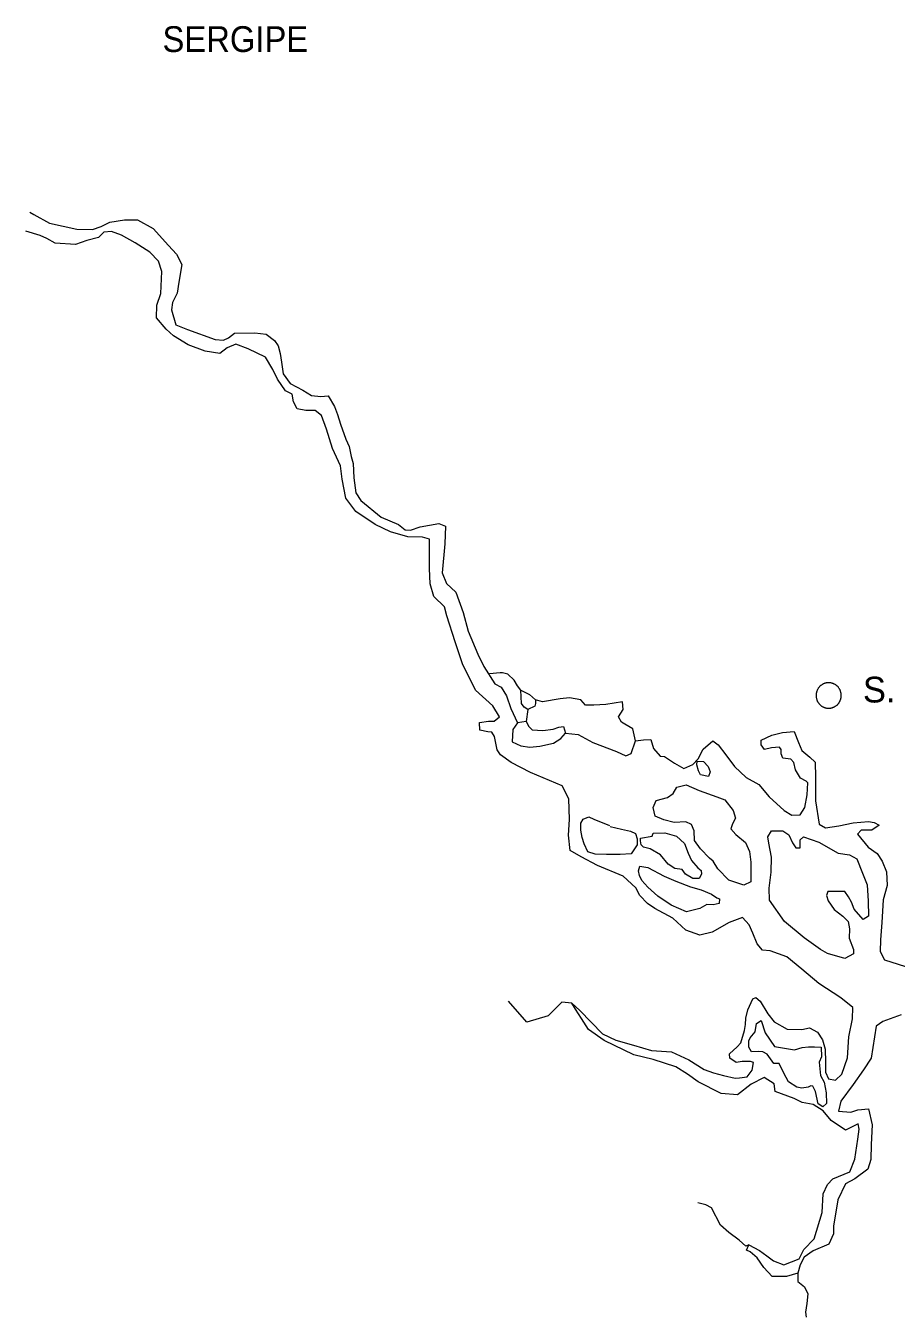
# Model space of a CAD drawing. Extents: x 47169 to 972804, y 7447977 to 9608469.
# Drawn here: x 674656 to 697299, y 8765455 to 8799042 of the extents above; entities that cross this region are included whole.
import ezdxf

# ---------------------------------------------------------------- set-up
doc = ezdxf.new("R2010")
doc.units = 0
doc.header["$LTSCALE"] = 270
doc.layers.add('1', color=7, linetype='Continuous', lineweight=13)
doc.layers.add('3', color=7, linetype='Continuous')

msp = doc.modelspace()

# ---------------------------------------------------------------- linework, layer by layer
at = {"layer": '1'}
for points in [[(674756.8, 8794197.7), (674865.8, 8794130.7), (675269.1, 8793907.4), (675978.9, 8793748.8), (676394.3, 8793746.5), (676613.3, 8793822.8), (676843.5, 8793932.2), (677226.5, 8793996.5), (677565.4, 8793994.7), (677968.7, 8793771.3), (678370.8, 8793326.7), (678577.3, 8793104.3), (678718, 8792838.1), (678639, 8792373.9), (678593.7, 8792086.5), (678472.2, 8791843.8), (678449.3, 8791655.9), (678556.5, 8791268.2), (678861.9, 8791144.9), (679582, 8790886.5), (679800.5, 8790863.2), (679932.1, 8790928.9), (680085.8, 8791049.7), (680610.6, 8791057.9), (680905.5, 8791023.1), (681123.2, 8790856), (681220.9, 8790722.7), (681274.5, 8790523.3), (681306, 8790290.8), (681348.1, 8789991.9), (681532.5, 8789736.5), (681859.5, 8789568.8), (682088.3, 8789423.7), (682328.7, 8789400.2), (682525.5, 8789421.3), (682688, 8789143.8), (682763.3, 8788933.2), (682838.4, 8788678.4), (682978.4, 8788290.4), (683064.8, 8788101.9), (683117.9, 8787836.1), (683171.6, 8787658.8), (683191.4, 8787282.6), (683243.9, 8786895.2), (683373.9, 8786695.3), (683896.2, 8786261), (684354.2, 8786070.4), (684528.3, 8785936.6), (684659.4, 8785924.8), (684911.3, 8786011.9), (685403.7, 8786097.7), (685578.2, 8786030.3), (685553.7, 8785565.8), (685483.9, 8784814), (685602.5, 8784536.8), (685841.7, 8784314.2), (686035.5, 8783782.1), (686163.8, 8783294.6), (686411.8, 8782695.9), (686573.9, 8782374.2), (686855.6, 8781930.1), (687019, 8781840.6), (687159.8, 8781618.6), (687278.1, 8781286), (687450.8, 8780908.9), (687329.7, 8780743.7), (687306, 8780423), (687534.8, 8780311.1), (687764.1, 8780276.6), (688026.6, 8780308.3), (688387.7, 8780383.6), (688574.2, 8780504.2), (688695.2, 8780647.3), (689022.9, 8780612.3), (689404.2, 8780399.9), (690025.7, 8780164), (690265.5, 8780052), (690408, 8780117.5), (690519.2, 8780448.7), (690727, 8780469.6), (690912.8, 8780479.6), (690988, 8780246.9), (691161.7, 8780046.7), (691270.9, 8780035), (691532.2, 8779867.6), (691771.8, 8779722.3), (692012.8, 8779831.6), (692144.8, 8779974.6), (692277.5, 8780228.2), (692530.1, 8780448), (692671.6, 8780336.6), (692866.8, 8780081), (693094.5, 8779780.9), (693398.8, 8779491.5), (693725.6, 8779312.6), (693996.9, 8778990.2), (694388.2, 8778633.8), (694584.2, 8778511), (694802.8, 8778520.7), (694924.2, 8778708.1), (694980.8, 8779039.6)], [(682638.2, 8788049), (682477, 8788547.7), (682347.8, 8788902.3), (682184.5, 8789036), (681944, 8789037.3), (681714.7, 8789082.8), (681617.3, 8789260.4), (681585.6, 8789459.6), (681411.2, 8789549.1), (681205.2, 8789848.9), (681086.3, 8790104), (680891.3, 8790425.8), (680444.3, 8790638.5), (680117, 8790761.9), (679897.8, 8790663.6), (679700.3, 8790520.8), (679318, 8790578.2), (678881.6, 8790746.5), (678500.3, 8790980.9), (678304.4, 8791147.9), (678054.6, 8791447.9), (678067.3, 8791779.7), (678167.3, 8792077.8), (678192.3, 8792652.9), (678106.3, 8792918.8), (677877.9, 8793152.3), (677496.6, 8793397.7), (677147.8, 8793598.7), (676885.9, 8793688.6), (676689.1, 8793678.6), (676546.2, 8793535.6), (676239.7, 8793459.8), (675944, 8793350.7), (675419.4, 8793386.7), (675201.4, 8793509.5), (675026.9, 8793587.9), (674655.8, 8793700.4)], [(690931, 8772392.9), (691455.3, 8772356.6), (691902, 8772143.8), (692304.8, 8771898), (692544.7, 8771808.1), (692806.5, 8771740.2), (693112, 8771672), (693221.3, 8771682.4), (693418.1, 8771703.3), (693550.3, 8771879.6), (693584.3, 8772078.5), (693507.9, 8772101.1), (693289.4, 8772102.4), (693136.3, 8772081.2), (692973.1, 8772192.7), (692962.8, 8772303.4), (693160.6, 8772490.3), (693259.5, 8772589.3), (693348.8, 8772909.6), (693382.5, 8773064.3), (693383.5, 8773230.2), (693439.5, 8773451.1), (693572.3, 8773737.9), (693649, 8773770.7), (693757.6, 8773670.5), (693963.3, 8773348.4), (694126, 8773137.3), (694463.6, 8772947.2), (694845.9, 8772933.8), (695042.9, 8772976.9), (695249.8, 8772865), (695379.7, 8772665.1), (695454.7, 8772421.3), (695463.7, 8772089.3), (695462.1, 8771823.9), (695537.6, 8771657.5), (695723.1, 8771623.2), (695887.9, 8771777.1), (696032.5, 8772196.6), (696068.6, 8772749.5), (696158.8, 8773213.6), (696171.5, 8773512.2), (695856.1, 8773757.5), (695290.2, 8774137), (694844.4, 8774504.7), (694453, 8774827.9), (694016.8, 8774985.4), (693820.2, 8774997.6), (693679.1, 8775164.4), (693571.5, 8775441.6), (693474.5, 8775663.4), (693300.7, 8775852.5), (692950.3, 8775721.8), (692511.7, 8775470), (692194.4, 8775394.4), (691823.6, 8775518.3), (691486.6, 8775830), (691018.3, 8776087.2), (690833.2, 8776210), (690626.8, 8776421.4), (690529.7, 8776621.1), (690192.7, 8776921.7), (689527.7, 8777202.2), (689102.8, 8777425.9), (688819.7, 8777593.4), (688778.2, 8777991.9), (688802.5, 8778401.1), (688783.7, 8778932.2), (688610.8, 8779276.1), (687782.2, 8779623.8), (687281, 8779881.1), (687009, 8780081.8), (686922.3, 8780215), (686847.7, 8780558.4), (686782.8, 8780669.4), (686673.6, 8780681.1), (686466.2, 8780726.5), (686456.4, 8780925.7), (686697, 8780957.5), (686839.1, 8780956.7), (686981.8, 8781066.5), (686808.6, 8781355.1), (686351.9, 8781767), (686016.9, 8782443.7), (685823.5, 8783020), (685608.7, 8783696), (685544.4, 8783928.7), (685272.7, 8784195.7), (685176.2, 8784528.1), (685156.6, 8784926.5), (685159.5, 8785435.3), (685160.9, 8785689.7), (684975.4, 8785746.1), (684592.8, 8785748.2), (684145.5, 8785883.5), (683742.1, 8786073.8), (683241.2, 8786408.4), (682980.8, 8786752.8), (682885.2, 8787251.1), (682843.3, 8787594.3), (682638.2, 8788049)], [(687532.2, 8781760.2), (687445.4, 8781871.4), (687358.9, 8782026.8), (687195.8, 8782182.6), (687053.9, 8782216.5), (686999.3, 8782216.9), (686714.9, 8782185.3)], [(690519.2, 8780448.7), (690444.5, 8780758.9), (690237.6, 8780881.8), (690150.4, 8780926.6), (690074.7, 8781070.8), (690196, 8781258.2), (690175.3, 8781457.4), (689748.7, 8781393.5), (689431.7, 8781373.2), (689213.1, 8781374.5), (689093.6, 8781507.9), (688798.9, 8781564.9), (688558.2, 8781533.1), (688098.8, 8781458.3), (687913.3, 8781514.7), (687912.8, 8781415.2), (687901.4, 8781348.8), (687715.1, 8781261.4), (687617.1, 8781317.3), (687552.1, 8781417.2), (687532.2, 8781760.2), (687761.1, 8781648.3), (687913.3, 8781514.7)], [(695870.5, 8781622.9), (695870.6, 8781634), (695869.6, 8781646.2), (695868.6, 8781657.3), (695867.5, 8781669.4), (695865.4, 8781680.5), (695863.3, 8781691.6), (695861.2, 8781703.8), (695858, 8781714.8), (695854.8, 8781725.9), (695851.6, 8781737), (695847.2, 8781747), (695842.9, 8781758.1), (695838.6, 8781769.2), (695833.2, 8781779.2), (695827.8, 8781789.1), (695821.3, 8781799.1), (695815.9, 8781809.1), (695809.4, 8781818), (695801.8, 8781828), (695795.3, 8781836.9), (695787.7, 8781845.8), (695780.1, 8781853.6), (695771.4, 8781862.5), (695763.8, 8781870.3), (695755.1, 8781878.1), (695746.4, 8781884.8), (695736.6, 8781892.6), (695727.9, 8781899.3), (695718.1, 8781904.8), (695708.3, 8781911.6), (695698.5, 8781917.1), (695688.7, 8781922.7), (695677.8, 8781927.2), (695666.9, 8781931.7), (695657.1, 8781936.2), (695646.2, 8781939.6), (695635.3, 8781943), (695624.4, 8781946.3), (695612.4, 8781948.6), (695601.5, 8781950.9), (695590.5, 8781953.2), (695578.5, 8781954.4), (695567.6, 8781955.5), (695555.6, 8781956.7), (695544.7, 8781956.8), (695533.7, 8781956.8), (695521.7, 8781955.8), (695510.8, 8781954.8), (695498.7, 8781953.7), (695487.8, 8781951.6), (695476.8, 8781949.4), (695464.8, 8781947.3), (695453.9, 8781944.1), (695442.9, 8781940.8), (695432, 8781937.5), (695422.1, 8781933.2), (695411.1, 8781928.8), (695400.2, 8781924.5), (695390.3, 8781919), (695380.5, 8781913.5), (695370.6, 8781906.9), (695360.7, 8781901.5), (695351.9, 8781894.9), (695342, 8781887.2), (695333.3, 8781880.6), (695324.5, 8781872.9), (695316.8, 8781865.2), (695308, 8781856.4), (695300.3, 8781848.7), (695292.6, 8781839.9), (695286, 8781831.1), (695278.2, 8781821.2), (695271.6, 8781812.4), (695266.1, 8781802.5), (695259.5, 8781792.5), (695254, 8781782.6), (695248.5, 8781772.7), (695244, 8781761.7), (695239.6, 8781750.6), (695235.2, 8781740.7), (695231.8, 8781729.7), (695228.5, 8781718.6), (695225.1, 8781707.6), (695222.8, 8781695.4), (695220.6, 8781684.4), (695218.3, 8781673.3), (695217.2, 8781661.2), (695216, 8781650.1), (695214.9, 8781637.9), (695214.8, 8781626.9), (695214.7, 8781615.8), (695215.8, 8781603.6), (695216.8, 8781592.6), (695217.8, 8781580.4), (695219.9, 8781569.3), (695222, 8781558.2), (695224.2, 8781546.1), (695227.4, 8781535), (695230.6, 8781523.9), (695233.8, 8781512.8)], [(695233.8, 8781512.8), (695238.1, 8781502.8), (695242.4, 8781491.7), (695246.7, 8781480.7), (695252.1, 8781470.7), (695257.5, 8781460.7), (695264, 8781450.7), (695269.4, 8781440.7), (695275.9, 8781431.8), (695283.5, 8781421.8), (695290, 8781412.9), (695297.6, 8781404), (695305.2, 8781396.2), (695313.9, 8781387.3), (695321.5, 8781379.5), (695330.2, 8781371.7), (695338.9, 8781365.1), (695348.7, 8781357.2), (695357.4, 8781350.6), (695367.2, 8781345), (695377, 8781338.3), (695386.8, 8781332.7), (695396.6, 8781327.1), (695407.5, 8781322.6), (695418.4, 8781318.1), (695428.2, 8781313.6), (695439.1, 8781310.2), (695450.1, 8781306.9), (695461, 8781303.5), (695473, 8781301.2), (695483.9, 8781298.9), (695494.8, 8781296.6), (695506.8, 8781295.4), (695517.7, 8781294.3), (695529.8, 8781293.1), (695540.7, 8781293.1), (695551.6, 8781293), (695563.6, 8781294), (695574.6, 8781295.1), (695586.6, 8781296.1), (695597.6, 8781298.2), (695608.5, 8781300.4), (695620.5, 8781302.5), (695631.5, 8781305.8), (695642.4, 8781309), (695653.4, 8781312.3), (695663.2, 8781316.7), (695674.2, 8781321), (695685.2, 8781325.4), (695695, 8781330.8), (695704.9, 8781336.3), (695714.8, 8781342.9), (695724.6, 8781348.4), (695733.4, 8781354.9), (695743.3, 8781362.6), (695752.1, 8781369.2), (695760.9, 8781376.9), (695768.6, 8781384.6), (695777.4, 8781393.4), (695785.1, 8781401.1), (695792.8, 8781409.9), (695799.4, 8781418.7), (695807.1, 8781428.6), (695813.7, 8781437.4), (695819.2, 8781447.4), (695825.8, 8781457.3), (695831.4, 8781467.2), (695836.9, 8781477.1), (695841.3, 8781488.2), (695845.8, 8781499.2), (695850.2, 8781509.1), (695853.5, 8781520.2), (695856.9, 8781531.2), (695860.2, 8781542.3), (695862.5, 8781554.4), (695864.7, 8781565.5), (695867, 8781576.5), (695868.2, 8781588.7), (695869.3, 8781599.7), (695870.5, 8781611.9), (695870.5, 8781622.9)], [(687715.1, 8781261.4), (687669.7, 8780951.9), (687450.8, 8780908.9)], [(687669.7, 8780951.9), (687745.4, 8780818.8), (687832.3, 8780729.8), (688105.5, 8780717.1), (688378.9, 8780748.7), (688521.2, 8780803.2), (688641.5, 8780813.6), (688695.2, 8780647.3)], [(694980.8, 8779039.6), (695004.5, 8779349.2), (694961, 8779393.7), (694808.5, 8779472.1), (694678.7, 8779694.1), (694636.1, 8779882.4), (694560.1, 8779971.4), (694352.6, 8779994.7), (694309.5, 8780105.6), (694310.2, 8780216.2), (694266.9, 8780282.9), (694059.1, 8780262), (693873.1, 8780218.8), (693786.3, 8780341), (693787.1, 8780462.7), (694061.1, 8780593.8), (694345.6, 8780658.5), (694640.9, 8780690), (694759.4, 8780401.6), (694845.6, 8780190.9), (695052.2, 8780023.8), (695193.5, 8779890.2), (695202.1, 8779502.9), (695198.4, 8778883.4), (695293.1, 8778274.4), (695456.5, 8778184.9), (695806.6, 8778238.2), (696178.6, 8778313.4), (696583.1, 8778344.1), (696725.1, 8778321.1), (696855.8, 8778254), (696669.2, 8778122.3), (696385.1, 8778124.1), (696297, 8778014), (696568.2, 8777680.4), (696807.6, 8777513.1), (696937.5, 8777313.2), (697045.2, 8777035.9), (697064.9, 8776681.8), (696964.2, 8776306.3), (696927.9, 8775720.2), (696892.4, 8775266.8), (696879.7, 8774968.2), (696998.5, 8774746.2), (697707.4, 8774520.7)], [(689861.4, 8778217.9), (690156.1, 8778149.9), (690385.2, 8778093.2), (690516.1, 8778037.1), (690558.9, 8777893.1), (690558, 8777738.2), (690403.7, 8777506.8), (690119.4, 8777486.3), (689758.8, 8777488.4), (689463.9, 8777501.2), (689278.4, 8777557.6), (689181.3, 8777768.3), (689127.6, 8777934.6), (689095.9, 8778122.8), (689096.9, 8778299.8), (689152.2, 8778410.1), (689305.5, 8778464.6), (689436.3, 8778408.5), (689839.7, 8778240.2)], [(688862.2, 8773621.8), (688600.1, 8773645.5), (688248.4, 8773293.5), (687690.2, 8773130.8), (687212.6, 8773675.6)], [(697427, 8773316.5), (696956, 8773142.4), (696780.5, 8773021.7), (696644.3, 8772192.9), (696445.8, 8771884.3), (696181.3, 8771509.8), (695861.8, 8771069.2), (695794.7, 8770815.2), (696122.3, 8770791), (696297.5, 8770845.3), (696581.8, 8770876.8), (696677.5, 8770455.8), (696652.6, 8769947.1), (696639.3, 8769559.9), (696561.3, 8769306), (696221.1, 8769053.6), (695979.9, 8768922.3), (695780.7, 8768503.1), (695667.3, 8767817.9), (695666.1, 8767618.8), (695544.4, 8767354), (695139.1, 8767179.5), (694908.7, 8767014.9), (694798.2, 8766816.4), (694742.3, 8766595.5), (694446.8, 8766508.8), (694075.4, 8766511), (693858.3, 8766744.7), (693685, 8767000.1), (693500.2, 8767156.1), (693402.2, 8767200.9), (693468.5, 8767333.3), (693740.8, 8767187.9), (693936.6, 8767053.9), (694110.6, 8766920.1), (694372.2, 8766819), (694777.3, 8766971.5), (694899, 8767214.1), (695162.8, 8767489.1), (695374.5, 8768173.7), (695399.3, 8768660.3), (695510, 8768903), (695653, 8769057), (696091.1, 8769231.4), (696224.2, 8769562.5), (696303.8, 8770081.9), (696338.2, 8770347.2), (696306.2, 8770480.2), (695977.4, 8770316.2), (695607.5, 8770572.9), (695401.4, 8770817.5), (695140.2, 8770985), (694856.4, 8771042.1), (694649.4, 8771142.9), (694147.9, 8771322.9), (694127.2, 8771522.1), (693866, 8771689.6), (693526.3, 8771514.6), (693175, 8771240.2), (692749.1, 8771275.9), (692150, 8771578.1), (691867.1, 8771778.9), (691562.3, 8771968.8), (690973.4, 8772160.3), (690471.4, 8772273.9), (689697.9, 8772654.5), (689295.2, 8772933.4), (689111.2, 8773222.1), (688959.6, 8773466.4), (688862.2, 8773621.8), (689068.7, 8773432.6), (689655.2, 8772820.7), (690003.9, 8772663.8), (690462, 8772528.4), (690931, 8772392.9)], [(693468.5, 8767333.3), (693391.9, 8767300.6), (693218, 8767456.5), (692946.1, 8767657.2), (692728.7, 8767846.6), (692491.1, 8768301.6), (692349.5, 8768379.9), (692142.2, 8768425.3)], [(694742.3, 8766595.5), (694741, 8766385.3), (694914.9, 8766240.5), (695001.3, 8766063), (694977.9, 8765808.7), (694943.8, 8765587.6), (694953.9, 8765454.8)]]:
    msp.add_lwpolyline(points, dxfattribs=at)
for points in [[(692208, 8779564.9), (692153.9, 8779664.8), (692111.1, 8779819.9), (692122.7, 8779919.4), (692286.5, 8779907.4), (692406, 8779773.9), (692459.8, 8779640.9), (692415.4, 8779519.4)], [(692630.8, 8778987.2), (692838, 8778908.5), (693054.9, 8778630.7), (693119.3, 8778431.2), (693042, 8778287.8), (692997.5, 8778155.3), (693127.8, 8778010.7), (693377.8, 8777799.1), (693485.8, 8777566.1), (693516.9, 8777289.4), (693513.9, 8776780.5), (693338.5, 8776693), (692945.8, 8776817.1), (692663.5, 8777117.4), (692533.5, 8777317.3), (692446.6, 8777395.2), (692207.6, 8777640), (692055.8, 8777851.1), (692046.4, 8778105.6), (691970.9, 8778272), (691829.2, 8778339.2), (691523.1, 8778318.9), (691250.3, 8778386.8), (691032.3, 8778487.7), (690979, 8778709.2), (691056.6, 8778896.8), (691352.1, 8778972.6), (691494.7, 8779071.3), (691594.1, 8779236.6), (691834.9, 8779301.6), (692172.8, 8779155.8)], [(690975.1, 8778045.5), (691281.1, 8778054.8), (691586.6, 8777964.5), (691793.1, 8777775.2), (691890, 8777520.2), (691976.3, 8777331.7), (692139.1, 8777142.6), (692226.1, 8777075.7), (692236.5, 8776976.1), (692170.3, 8776865.9), (692006.3, 8776866.8), (691821.2, 8776978.6), (691734.5, 8777100.8), (691538, 8777124), (691363.8, 8777235.7), (691168.5, 8777480.2), (690896.2, 8777636.7), (690721.6, 8777681.9), (690667.3, 8777737.6), (690646.1, 8777848.3), (690646.5, 8777914.7), (690952.8, 8777968.2)], [(694392.9, 8775746.4), (694002.8, 8776301.9), (693993.7, 8776611.7), (694050.8, 8777031.8), (694053.1, 8777418.9), (693989.7, 8777784.4), (693958, 8777950.5), (694057.2, 8778104.8), (694352.3, 8778103), (694504.7, 8778002.6), (694601.8, 8777791.8), (694688.4, 8777658.5), (694797.7, 8777657.9), (694798.9, 8777868.1), (694886.8, 8777945), (695290.4, 8777809.8), (695791.3, 8777519.2), (696086.2, 8777484.2), (696271.3, 8777372.5), (696422.1, 8777006.5), (696540.4, 8776696), (696570.7, 8776275.5), (696579.2, 8775888.2), (696436.7, 8775800.6), (696208.8, 8776067.4), (696133.4, 8776244.9), (696057.7, 8776389.2), (695960.2, 8776522.5), (695741.6, 8776523.8), (695523.1, 8776525.1), (695489.7, 8776425.8), (695532.6, 8776281.7), (695684.2, 8776059.5), (695912.6, 8775881.2), (696053.9, 8775747.6), (696085.5, 8775559.3), (696073.1, 8775316), (696191.5, 8775016.6), (696190.9, 8774906), (695960.7, 8774785.7), (695513.4, 8774910), (695328.3, 8775021.8), (694903.9, 8775323)], [(691568.8, 8776792), (691950.4, 8776645.9), (692223.1, 8776566.9), (692495.7, 8776454.7), (692637.2, 8776365.3), (692702.6, 8776331.8), (692690.9, 8776210.1), (692537.7, 8776177.8), (692373.9, 8776189.9), (692187.5, 8776080.3), (691848.2, 8775993.8), (691445, 8776173.2), (691096.6, 8776407.6), (690835.8, 8776641.4), (690683.7, 8776808.2), (690619, 8776941.4), (690597.8, 8777063.2), (690631.3, 8777184.7), (690838.7, 8777150.3), (691263.6, 8776926.5)], [(694119.5, 8772053.2), (693946.1, 8772297.6), (693826.3, 8772353.6), (693728, 8772365.3), (693531.3, 8772355.4), (693466.4, 8772477.4), (693467.4, 8772643.4), (693500.7, 8772720.6), (693632.7, 8772874.7), (693666.8, 8773095.8), (693787.5, 8773172.5), (693894.8, 8772851), (694133.1, 8772495.6), (694657, 8772404), (694854.1, 8772469.2), (695018.1, 8772490.3), (695171, 8772489.4), (695345.8, 8772477.3), (695355.2, 8772222.8), (695299.8, 8772090.3), (695330.4, 8771736.2), (695427.8, 8771569.6), (695480.7, 8771292.7), (695490, 8771016.1), (695391.1, 8770928.2), (695271.4, 8771006.4), (695196.8, 8771327.6), (695132.1, 8771460.8), (695077.5, 8771472.2), (695011.8, 8771439.4), (694847.7, 8771407.2), (694716.8, 8771441.1), (694499.1, 8771575.2), (694380.2, 8771797.2), (694250.6, 8772052.4)]]:
    msp.add_lwpolyline(points, close=True, dxfattribs=at)

# ---------------------------------------------------------------- texts
at = {"layer": '3', "width": 0.95}
msp.add_text('SERGIPE', height=671.1, dxfattribs=at).set_placement((678212.1, 8798360.6))
at = {"layer": '3'}
msp.add_text('S. CRISTOVÃO', height=670.8, dxfattribs=at).set_placement((696434.2, 8781442))

doc.saveas('drawing.dxf')
